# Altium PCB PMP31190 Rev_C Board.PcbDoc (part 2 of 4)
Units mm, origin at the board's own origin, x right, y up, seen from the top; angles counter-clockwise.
Board outline 175.26 x 91.44 mm, 4 copper layers (Top Layer, Mid-Layer 1, Mid-Layer 2, Bottom Layer), stack 1.473 mm thick; 252 components, 140 nets, 735 pads, 501 vias.
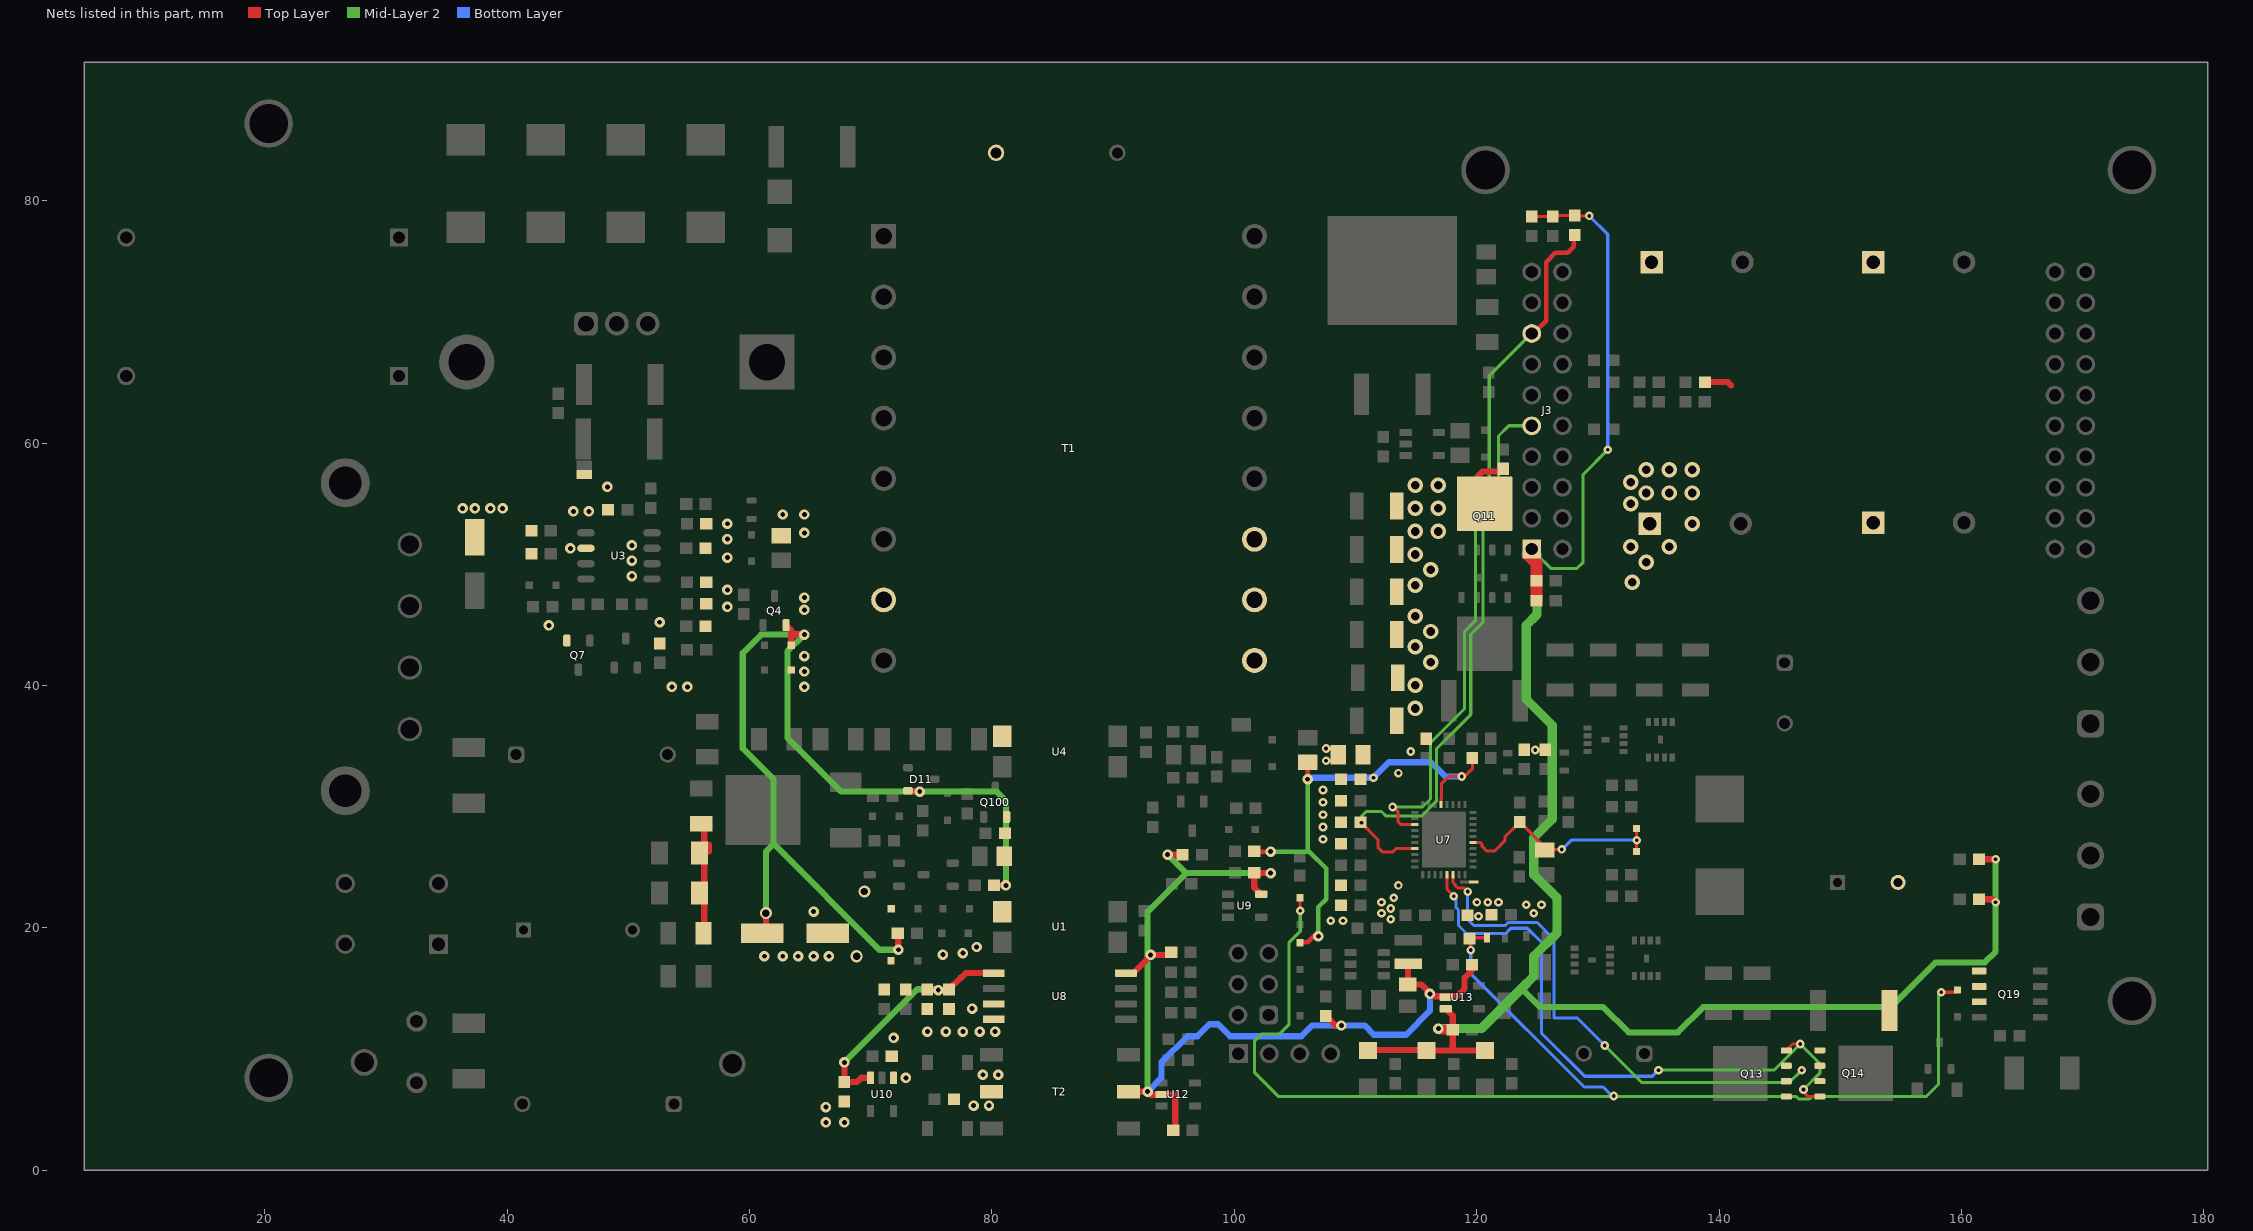
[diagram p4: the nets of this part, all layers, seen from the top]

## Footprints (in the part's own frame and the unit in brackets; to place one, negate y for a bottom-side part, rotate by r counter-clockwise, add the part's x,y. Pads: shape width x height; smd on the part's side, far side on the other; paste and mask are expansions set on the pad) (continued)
FP-750320256r00H_TRANSFORMER_41MM9_44MM0-MFG [mm]
  rrect5% 2.05x2.05 hole 1.35 paste-2539.97 mask+0: 1(-15.3,17.5)
  round 2.05 hole 1.35 paste-2539.97 mask+0: 2(-15.3,12.5) 3(-15.3,7.5) 4(-15.3,2.5) 5(-15.3,-2.5) 6(-15.3,-7.5) 7(-15.3,-12.5) 8(-15.3,-17.5) 9(15.3,-17.5) 10(15.3,-12.5) 11(15.3,-7.5) 12(15.3,-2.5) 13(15.3,2.5) 14(15.3,7.5) 15(15.3,12.5) 16(15.3,17.5)
  silkscreen extent -21.57,-22 20.95,22, body extent -21.05,-22.1 21.05,22.1, height 0.25
FP-560050316012_0603-MFG [mm]
  rrect20% 0.5x0.8 smd paste+0 mask+0: 1(-0.75,0) 2(0.75,0)
  silkscreen extent -0.13,-0.48 0.13,0.48, body extent -1.1,-0.58 1.1,0.58, height 0.25
FP-EKZM350ELL681MJ25S_RADIAL-MFG [mm]
  rrect8% 1.25x1.25 hole 0.75 paste-2539.97 mask+0: 1(-2.5,0)
  round 1.25 hole 0.75 paste-2539.97 mask+0: 2(2.5,0)
  silkscreen extent -5.25,-5.25 5.25,5.25, body extent -5.35,-5.35 5.35,5.35, height 0.25
FP-SQ9407EY-T1_GE3_SO-8-MFG [mil]
  rrect18% 47x22 smd paste+0 mask+0: 1(-99.5,75) 2(-99.5,25) 3(-99.5,-25) 4(-99.5,-75) 5(99.5,-75) 6(99.5,-25) 7(99.5,25) 8(99.5,75)
  silkscreen extent -149,-98 61,98, body extent -127,-102 127,102, height 10
FUSE_392 [mm] "LITTELFUSE"
  round 1.7 hole 1.05: 1(-2.54,0) 2(2.54,0)
  silkscreen extent -4.32,-2.03 4.32,2.03, body extent -4.25,-2 4.25,2, height 8
GBU [mm] "Comchip / Diodes Inc diode bridge"
  round 2 hole 1.5: 1(-7.62,0) 2(-2.54,0) 3(2.54,0) 4(7.62,0)
  silkscreen extent -11.15,-2.28 11.15,1.28, body extent -11.15,-2.28 11.15,1.28, height 21.55
HSINK_V6560W [mm] "Heat Sink TO-220"
  round 4.05 hole 2.7: 1(-12.7,0) 2(12.7,0)
  body extent -15,-9 15,3, height 25
IEC_HighVoltage_Small [mm]
  silkscreen extent -2.72,-2.24 2.72,2.47
IEC_HotSurface_Small [mm]
  silkscreen extent -2.72,-2.36 2.72,2.35
Keystone5012 [mil] "Keystone Multipurpose loops"
  round 87 hole 63: 1(0,0)
  silkscreen extent -70,-70 70,70, body extent -63,-63 63,62, height 319
MINI-SMA [mm] "COMCHIP"
  rect 1.4x1.9 smd: 1(-1.65,0) 2(1.65,0)
  silkscreen extent -3,-1.3 2.4,1.3, body extent -1.95,-0.9 1.95,0.9, height 1.7
Net-Tie_10milWide_30milLong [mil] "10mil net tie, no solder mask opening, no solder paste"
  rect 30x10 smd paste-5 mask-5: 1(-15,0) 2(15,0)
Net-Tie_50milWide_30milLong [mil] "50mil net tie, no solder mask opening, no solder paste"
  rect 30x50 smd paste-20 mask-20: 1(-15,0) 2(15,0)
Power_WDFN-8 [mm] "SMD, 8-Leads, Body 3.3x3.3mm, Pitch 0.65mm"
  rect 0.66x0.42 smd: 1(-1.47,0.975) 2(-1.47,0.325) 3(-1.47,-0.325) 4(-1.47,-0.975) 5(1.47,-0.975) 6(1.47,-0.325) 7(1.47,0.325) 8(1.47,0.975) 9(0,0)
  Top Layer region: 0.25,1.73 -0.32,1.73 -0.32,1.185 -0.5,1.185 -0.5,-1.185 -0.32,-1.185 -0.32,-1.73 0.25,-1.73 0.25,-1.185 1.33,-1.185 1.33,1.185 0.25,1.185
  silkscreen extent -1.9,-1.65 1.65,1.75, body extent -1.65,-1.65 1.65,1.65, height 0.81
RRV0036A-MFG [mm]
  rrect40% 0.6x0.25 smd paste+0 mask+0: 1(-2.4,2.25) 2(-2.4,1.75) 3(-2.4,1.25) 4(-2.4,0.75) 5(-2.4,0.25) 6(-2.4,-0.25) 7(-2.4,-0.75) 8(-2.4,-1.25) 9(-2.4,-1.75) 10(-2.4,-2.25) 19(2.4,-2.25) 20(2.4,-1.75) 21(2.4,-1.25) 22(2.4,-0.75) 23(2.4,-0.25) 24(2.4,0.25) 25(2.4,0.75) 26(2.4,1.25) 27(2.4,1.75) 28(2.4,2.25)
  rrect40% 0.25x0.6 smd paste+0 mask+0: 11(-1.75,-2.9) 12(-1.25,-2.9) 13(-0.75,-2.9) 14(-0.25,-2.9) 15(0.25,-2.9) 16(0.75,-2.9) 17(1.25,-2.9) 18(1.75,-2.9) 29(1.75,2.9) 30(1.25,2.9) 31(0.75,2.9) 32(0.25,2.9) 33(-0.25,2.9) 34(-0.75,2.9) 35(-1.25,2.9) 36(-1.75,2.9)
  rrect3% 3.6x4.6 smd paste-1000 mask+0: 37(0,0)
  silkscreen extent -3.4,-3.05 2.55,3.05, body extent -2.8,-3.3 2.8,3.3, height 0.25
Samtec_HTSW-103-07-x-D [mm] "Header, 2.54mm, 3x2, Gold, TH"
  rrect50% 1.55x1.55 hole 1.02: 1(-1.27,2.54)
  round 1.55 hole 1.02: 2(1.27,2.54) 3(-1.27,0) 4(1.27,0) 5(-1.27,-2.54) 6(1.27,-2.54)
  silkscreen extent -2.61,-3.91 2.61,4.3, body extent -2.51,-3.81 2.51,3.81, height 8.38
SMA [mm] "Molded Diode, 2-Leads, Body 4.3x2.6mm, IPC Medium Density, based on OnSemi component dimensions and land pattern"
  rect 2x2 smd: 1(-2,0) 2(2,0)
  silkscreen extent -3.66,-1.57 2.79,1.57, body extent -2.6,-1.3 2.6,1.3, height 2.42
SMC_265 [mm] "SMD, 2-Leads, Body 7.15x6.25mm"
  rect 2.6x3.2 smd: 1(-3.6,0) 2(3.6,0)
  silkscreen extent -5.6,-3.23 5.3,3.22, body extent -4.07,-3.13 4.07,3.13, height 2.65
SMD-4 [mm] "SMD, 4-Leads, Body 4.83x6.81mm, Pitch 2.54mm"
  rect 1.525x1.78 smd: 1(-4.763,1.27) 2(-4.763,-1.27) 3(4.763,-1.27) 4(4.763,1.27)
  silkscreen extent -3.5,-2.42 3.41,2.8, body extent -5.02,-2.42 5.02,2.42, height 3.91
SOD-123 [mm] "On Semi recommended land pattern"
  rect 0.915x1.22 smd: 1(-1.637,0) 2(1.637,0)
  silkscreen extent -2.74,-1.17 2.03,1.17, body extent -1.93,-0.9 1.93,0.9, height 1.35
SOD-323 [mm] "NXP recommended land pattern"
  rect 0.6x0.6 smd paste-0.05: 1(-1.1,0) 2(1.1,0)
  silkscreen extent -2.06,-0.86 1.53,0.86, body extent -1.3,-0.67 1.3,0.68, height 1.1
SOD-323F [mm] "NXP recommended land pattern"
  rect 0.6x0.6 smd paste-0.05: 1(-1.1,0) 2(1.1,0)
  silkscreen extent -2.06,-0.86 1.53,0.86, body extent -1.35,-0.67 1.35,0.68, height 0.79
SOT-23 [mm] "SOT23, 3-Leads, Body 2.9x1.3mm, Pitch 0.95mm, Lead Span 2.5mm, IPC Medium Density"
  rrect50% 1x0.6 smd: 1(-1.2,0.95) 2(-1.2,-0.95) 3(1.2,0)
  silkscreen extent -1.62,-1.5 0.7,1.5, body extent -1.16,-1.45 1.21,1.45, height 1
SOT-23L [mm] "SOT23, 3-Leads, Body 2.9x1.3mm, Pitch 0.95mm, Lead Span 2.5mm, IPC High Density"
  rrect50% 0.8x0.6 smd: 1(-1.1,0.95) 2(-1.1,-0.95) 3(1.1,0)
  silkscreen extent -1.5,-1.5 0.7,1.5, body extent -1.16,-1.45 1.21,1.45, height 1
TO-220FP [mm] "FM, Body 10.4x4.6mm, Pitch 2.55mm"
  rrect50% 1.95x1.95 hole 1.3: 1(-2.55,0)
  round 1.95 hole 1.3: 2(0,0) 3(2.55,0)
  silkscreen extent -5.1,-1.5 5.08,3, body extent -5.09,-1.5 5.09,3, height 19.41
WCAP-FTX2_1500x850 [mm] "TH, 2-Leads, Body 15x8.5mm"
  rrect50% 1.35x1.35 hole 0.9: 1(-6.25,0)
  round 1.35 hole 0.9: 2(6.25,0)
  body extent -7.5,-4.25 7.5,4.25, height 14
WCAP-PTHT_1000x1250 [mm] "TH, 2-Leads, Dia 10mm, Lead Sapcing 5mm"
  rrect50% 1.35x1.35 hole 0.9: 1(-2.5,0)
  round 1.35 hole 0.9: 2(2.5,0)
  body extent -5.25,-5.25 5.26,5.25, height 14.01
WE-CMB_Type_S [mm] "TH, 4-Leads, Body 14.7x13mm"
  rect 1.6x1.6 hole 1.1: 1(-3.85,2.5)
  round 1.6 hole 1.1: 2(-3.85,-2.5) 3(3.85,-2.5) 4(3.85,2.5)
  silkscreen extent -7.8,-6.5 7.35,6.5, body extent -7.77,-6.5 7.77,6.5, height 20
WE-HC6 [mm] "Wurth Electronik recommended land pattern"
  rect 3.85x4 smd: 1(-3.825,0) 2(3.825,0)
  silkscreen extent -6.2,-6.2 6.2,6.2, body extent -5.76,-5.36 5.74,5.34, height 5
WE-MAPI_2510 [mm] "SMD, 2-Leads, Body 2.7x2.2mm"
  rect 0.85x2.3 smd: 1(-0.975,0) 2(0.975,0)
  silkscreen extent -0.15,-1.1 0.15,1.1, body extent -1.25,-1 1.25,1, height 1
WL_SMCW_GREEN_1206 [mm] "SMD, 2-Leads, Body 3.2x1.6mm, Pitch 3mm"
  rect 1.4x1.5 smd: 1(-1.5,0) 2(1.5,0)
  silkscreen extent -2.9,-1.1 2.2,1.1, body extent -1.6,-0.85 1.6,0.85, height 0.78
Wurth_750313638 [mm] "SMD, 6-Leads, Body 8x9.14mm, Pitch 3.05mm"
  rect 1.9x1.14 smd: 1(-5.655,3.05) 2(-5.655,0) 3(-5.655,-3.05) 4(5.655,-3.05) 5(5.655,0) 6(5.655,3.05)
  silkscreen extent -4,-4.57 4,4.88, body extent -6.35,-4.57 6.35,4.57, height 7.62
Wurth_691236510003 [mm] "Terminal Block, 5.08mm, 3x1, R/A, TH"
  rrect50% 2.25x2.25 hole 1.5: 1(-5.08,0)
  round 2.25 hole 1.5: 2(0,0) 3(5.08,0)
  body extent -8.22,-5.5 7.62,5.85, height 18

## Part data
C1: library part CMP-0077651-1, "CAP, Safety, 2200 pF, 250VAC,+/- 20%, X1-Y1, D9xT4mm", Cap_Case=9x4x10mm, Manufacturer=MuRata, Supplier Part Number 1=490-DE1E3RA222MA4BN01F-ND, TempCo=B, Tolerance_%=10%, ValueDisplayed=2200pF
C2 C3: library part CMP-0012429-3, "CAP, Film, 0.68 uF, 630 V, +/- 20%, TH", Manufacturer=TDK, Supplier Part Number 1=495-4208-ND, Tolerance_%=20%, Value1=Unknown, Value2=630V, ValueDisplayed=0.68uF
C4 C5: library part CMP-0084596-1, "CAP, Film, 0.33 µF, X2 275 VAC, +/- 10%, TH", Cap_Case=15x8.5mm, Manufacturer="Wurth Elektronik", Tolerance_%=10%, ValueDisplayed=0.33µF
C6 C17 C51 C58 C70 C72 C73: library part CMP-0064933-4, "CAP, CERM, 1000 pF, 50 V,+/- 10%, X7R, 0603", Cap_Case=0603, Manufacturer="Wurth Elektronik", Supplier Part Number 1=732-8001-1-ND, TempCo=X7R, Tolerance_%=10%, Value1=Unknown, Value2=50V, ValueDisplayed=1000pF
C7 C8 C9 C10: library part CMP-0010013-3, "CAP, AL, 2200 uF, 50 V, +/- 20%, 0.018 ohm, TH", AC_Derating=0.35, Manufacturer=Rubycon, Tolerance_%=20%, Value1="0.018 ohm", Value2=50V, ValueDisplayed=2200uF
C11: library part CMP-0010802-1, "CAP, AL, 22 uF, 35 V, +/- 20%, SMD", Cap_Case=E55, Manufacturer=Wuerth, Tolerance_%=20%, Value1=Unknown, Value2=35V, ValueDisplayed=22uF
C12 C16 C62 C76 C100: library part CMP-0007696-2, "CAP, CERM, 1 uF, 50 V, +/- 10%, X7R, 0805", Cap_Case=0805, Manufacturer="Wurth Elektronik", Supplier Part Number 1=710-885012207103, TempCo=X7R, Tolerance_%=10%, Value1=Unknown, Value2=50V, ValueDisplayed=1uF
C13: library part CMP-0010800-1, "CAP, AL, 100 uF, 35 V, +/- 20%, SMD", Cap_Case=F80, Manufacturer=Panasonic, Tolerance_%=20%, Value1=Unknown, Value2=35V, ValueDisplayed=100uF
C14: library part CMP-0007872-2, Cap_Case=0805, Manufacturer=TDK, TempCo=X7R, Tolerance_%=10%, Value1=Unknown, Value2=50V
C15: library part CMP-0006825-5, "CAP, CERM, 2.2 uF, 16 V, +/- 20%, X5R, 0603", Cap_Case=0603, Manufacturer="Wurth Elektronik", Supplier Part Number 1=732-7915-1-ND, TempCo=X5R, Tolerance_%=20%, Value1=Unknown, Value2=16V, ValueDisplayed=2.2uF
C18 C22 C45 C46 C48 C49 C52 C55 C56 C59 C61 C64 C69 C77: library part CMP-0006837-3, "CAP, CERM, 0.1 uF, 50 V, +/- 10%, X7R, 0603", Cap_Case=0603, Manufacturer="Wurth Elektronik", TempCo=X7R, Tolerance_%=10%, Value1=Unknown, Value2=50V, ValueDisplayed=0.1uF
C19: library part CMP-0008950-2, "CAP, CERM, 10 uF, 25 V, +/- 10%, X5R, 1206", Cap_Case=1206, Manufacturer=Wuerth, TempCo=X5R, Tolerance_%=10%, Value1="0.004 ohm", Value2=25V, ValueDisplayed=10uF
C20 C23: library part CMP-0006761-4, "CAP, CERM, 10 pF, 50 V, +/- 5%, C0G/NP0, 0603", Cap_Case=0603, Manufacturer=Wuerth, TempCo=C0G/NP0, Tolerance_%=5%, Value1="0.403 ohm", Value2=50V, ValueDisplayed=10pF
C21: library part CMP-0006822-4, "CAP, CERM, 100 pF, 50 V, +/- 5%, C0G/NP0, 0603", Cap_Case=0603, Manufacturer="Wurth Elektronik", TempCo=C0G/NP0, Tolerance_%=5%, Value1=Unknown, Value2=50V, ValueDisplayed=100pF
C24: library part CMP-0085252-1, "CAP, CERM, 0.047 µF, 50 V,+/- 5%, X7R, 0603", Cap_Case=0603, Manufacturer=Wuerth, TempCo=X7R, Tolerance_%=5%, Value2=50V, ValueDisplayed=0.047µF
C25: library part CMP-0007975-2, "CAP, CERM, 2.2 uF, 25 V, +/- 10%, X7R, AEC-Q200 Grade 1, 0805", Cap_Case=0805, Manufacturer=TDK, Supplier Part Number 1=445-6965-1-ND, TempCo=X7R, Tolerance_%=10%, Value1=Unknown, Value2=25V, ValueDisplayed=2.2uF
C26: library part CMP-0750039-1, "CAP, CERM, 0.01 µF, 50 V,+/- 10%, X7R, 0603", Cap_Case=0603, Manufacturer="Wurth Elektronik", TempCo=X7R, Tolerance_%=10%, Value2=50V, ValueDisplayed=0.01µF
C29 C30 C31 C32 C36 C37 C38 C39 C40 C41 C42 C43: library part CMP-0081135-1, "CAP, CERM, 10 µF, 50 V,+/- 10%, X7R, 1210", Cap_Case=1210, Manufacturer=Wuerth, TempCo=X7R, Tolerance_%=10%, Value1="0.001 ohm", Value2=50V, ValueDisplayed=10µF
C33 C44: library part CMP-0079638-1, "CAP, Aluminum Polymer, 100 µF, 35 V,+/- 20%, 0.022 ohm, TH", Cap_Case=10x14mm, Manufacturer="Wurth Elektronik", Supplier Part Number 1=732-11917-1-ND, Tolerance_%=20%, Value1="0.022 ohm", Value2=35V, ValueDisplayed=100µF
C34 C35: library part CMP-0007097-4, "CAP, CERM, 0.47 uF, 50 V, +/- 10%, X7R, AEC-Q200 Grade 1, 0603", Cap_Case=0603, Manufacturer=TDK, Supplier Part Number 1=445-172475-1-ND, TempCo=X7R, Tolerance_%=10%, Value1=Unknown, Value2=50V, ValueDisplayed=0.47uF
C47: library part CMP-0007696-2, "CAP, CERM, 4.7 uF, 25 V, +/- 10%, X5R, 0805", Cap_Case=0805, Manufacturer="Wurth Elektronik", TempCo=X5R, Tolerance_%=10%, Value1=Unknown, Value2=25V, ValueDisplayed=4.7uF
C50 C53 C54 C57 C60 C65 C66 C67 C68: library part CMP-0006833-4, "CAP, CERM, 1 uF, 25 V, +/- 10%, X7R, 0603", Cap_Case=0603, Manufacturer="Wurth Elektronik", Supplier Part Number 1=732-7994-1-ND, TempCo=X7R, Tolerance_%=10%, Value1=Unknown, Value2=25V, ValueDisplayed=1uF
C63: library part CMP-0078154-1, "CAP, CERM, 10 µF, 16 V,+/- 20%, X5R, 0805", Cap_Case=0805, Manufacturer="Wurth Elektronik", Supplier Part Number 1=732-7624-1-ND, TempCo=X5R, Tolerance_%=20%, Value2=16V, ValueDisplayed=10µF
C74 C75: library part CMP-0081135-1, "CAP, CERM, 10 µF, 50 V,+/- 10%, X7R, 1210", Cap_Case=1210, Manufacturer=MuRata, Supplier Part Number 1=490-10961-1-ND, TempCo=X7R, Tolerance_%=10%, Value1="0.001 ohm", Value2=50V, ValueDisplayed=10µF
C101: library part CMP-0001423-1, "Cap Aluminum 470uF 35V 20% (10 X 16mm) Radial 5mm", Leakage Current=238uA, Manufacturer="United Chemi-Con", Operating Temperature Range="-40°C to +105°C", Tolerance_%=20%, ValueDisplayed=470µF
D1 D2 D12 D13 D16: library part CMP-0077069-2, "Diode, Standard Recovery Rectifier, 250 V, 0.2 A, SOD-323", Manufacturer="Micro Commercial Components", Value1=0.2A, Value2=1.25V
D3: library part CMP-0029241-1, "Diode, P-N-Bridge, 600 V, 4 A, TH", Manufacturer="Micro Commercial Components", Supplier Part Number 1=GBU4J-BPMS-ND, Value1=4A, Value2=1V
D4 D5 D103 D104: library part CMP-0005730-3, "Diode, TVS, Uni, 43 V, 69.4 Vc, SMC", Manufacturer="Wuerth Electronic", Value1=1500W
D6: library part CMP-0029033-2, "Diode, Ultrafast, 600 V, 1 A, AEC-Q101, SMA", Manufacturer="ON Semiconductor", Value1=1A, Value2=1.05V
D7: library part CMP-0005835-4, "Diode, Zener, 18 V, 200 mW, SOD-323", Manufacturer="Central semiconductor", Power_W=200mW, Value1=0.2W
D8 D15: library part CMP-0085758-1, "Diode, Zener, 12 V, 300 mW, SOD-323", Manufacturer="Central semiconductor", Power_W=300mW, Value1=0.3W
D9 D10: library part CMP-0076945-2, "Diode, P-N, 600 V, 1 A, MINI-SMA", Manufacturer="Taiwan semiconductor corporation", Value1=1A, Value2=1.1V
D11: library part CMP-0077061-2, "Diode, Switching, 70 V, 0.25 A, AEC-Q101, SOT-23", Manufacturer=Vishay-Semiconductor, Value1=0.25A, Value2=1.25V
D14 D25 D29 D100: library part CMP-0005833-4, "Diode, Zener, 15 V, 200 mW, SOD-323", Manufacturer="Central semiconductor", Power_W=200mW, Value1=0.2W
D17: library part CMP-0005839-4, "Diode, Zener, 27 V, 200 mW, SOD-323", Manufacturer="Diodes Inc.", Power_W=200mW, Value1=0.2W
D18 D19 D26 D27 D28: library part CMP-0076946-2, "Diode, Schottky, 100 V, 0.25 A, SOD-323F", Manufacturer=Nexperia, Value1=0.25A, Value2=0.85V
D20 D21 D22: library part CMP-0002936-3, "LED, Green, SMD", Color=Green, Manufacturer="Wurth Elektronik", Power_TotalModule=72mW, Value1=0.072W, Value2=2V
D23 D24: library part CMP-0028525-2, "Diode, Schottky, 30 V, 0.5 A, SOD-123", Manufacturer="ON Semiconductor", Value1=0.5A, Value2=0.43V
D30: library part CMP-0005786-2, "Diode, Zener, 5.1 V, 500 mW, SOD-123", Manufacturer="ON Semiconductor", Power_W=500mW, Value1=0.5W
D31: library part CMP-0076970-1, "Diode, Schottky, 40 V, 0.2 A, SOT-23", Manufacturer="Diodes Inc.", Supplier Part Number 1=BAS40-04FDICT-ND, Value1=0.2A, Value2=1V
D101: library part CMP-0076946-2, "Diode, Schottky, 100 V, 0.25 A, SOD-323F", Manufacturer=Nexperia, PartNumber=BAT46WJ,115, Value1=0.25A, Value2=0.85V
D102: library part CMP-0085758-1, "Diode, Zener, 28 V, 250 mW, SOD-323", Manufacturer="Central semiconductor", Power_W=250mW, Value1=0.25W
F1: library part CMP-0003561-2, "Fuse, 3.15 A, 250VAC/VDC, TH", Irating_A=3.15A, Manufacturer=Littelfuse, Supplier Part Number 1=F5504CT-ND
H1: library part CMP-0086362-1, "Heat Sink TO-220", Manufacturer="Assman WSW"
H2: library part CMP-0095825-2, "Heat Sink Passive TO-220 Straight Copper 12.5°C/W Matte Tin", Digikey Part Number=6230DG(COPPER)-ND, Manufacturer=Aavid, Mating Package=TO-220, Mouser Part Number=532-6230DG, Operating Temperature Range=to
J1 J2: library part CMP-0079043-1, "Terminal Block, 5.08mm, 3x1, R/A, TH", Color=Green, Current_A=20A, Manufacturer="Wurth Elektronik", Supplier Part Number 1=732-10996-ND, Voltage_V=300V
J3: library part CMP-0003837-4, "Receptacle, 2.54mm, 10x2, Tin, TH", Alternate Manufacturer="Major League Electronics", Alternate PartNumber=CRD-081413-A-G, Manufacturer=Wuerth
J4: library part CMP-0078266-4, "Receptacle, 2.54mm, 10x2, Tin, TH", Alternate Manufacturer="Major League Electronics", Alternate PartNumber=CRD-081413-A-G, Manufacturer=Wuerth
J5: library part CMP-0089047-1, Current_A=4A, Manufacturer=Molex, Voltage_V=500V
J6: library part CMP-0055587-1, "Header, 2.54mm, 3x2, Gold, TH", Color=Natural, Manufacturer=Samtec, Supplier Part Number 1=HTSW-103-07-G-D-ND
L1: library part CMP-0091284-1, "300µH Unshielded Toroidal Inductor 2.5A 150mOhm Max Radial, Vertical (Open)", Manufacturer="Wurth Electronics", Operating Temperature Range="-40°C to +105°C", Test Frequency=10kHz, Tolerance_%=20%
L2: library part CMP-0013143-1, "Coupled inductor, 2.2 mH,  A, 0.07 ohm, TH", Manufacturer="Wurth Elektronik", Supplier Part Number 1=732-1440-ND, ValueDisplayed=2.2mH
L3: library part CMP-0063967-1, "Inductor, Shielded Drum Core, Superflux, 5.5 uH, 10 A, 0.0112 ohm, SMD", Manufacturer="Wurth Elektronik", Supplier Part Number 1=732-1171-1-ND, Value1="0.0112 ohm", Value2=10A, ValueDisplayed=5.5uH
L4: library part CMP-0750073-1, "Inductor, Shielded, Metal Composite, 10 µH, 0.6 A, 0.733 ohm, SMD", Manufacturer="Wurth Elektronik", Value1="0.733 ohm", Value2=0.6A, ValueDisplayed=10µH
LOGO1 LOGO2 LOGO3 LOGO4: library part CMP-0074835-1, "IEC 61010-1 High Voltage Warning"
Logo5: library part CMP-0074837-2, "IEC 61010-1 Hot Surface Warning", Manufacturer="Texas Instruments"
NT1 NT2: library part CMP-0078142-5, "Single point connection between nets.", Manufacturer=N/A
Q1 Q3 Q4 Q7 Q100: library part CMP-0000387-2, "Transistor, NPN, 40 V, 0.2 A, SOT-23", Manufacturer="Diodes Inc.", Supplier Part Number 1=MMBT3904-FDICT-ND, Value1="0.2 A", Value2=400
Q2: library part CMP-0001269-3, "MOSFET, N-CH, 560 V, 7.6 A, DPAK", Alternate Manufacturer=None, Manufacturer="Infineon Technologies", Value1=1, Value2="26 nC"
Q5: library part CMP-0001215-2, "MOSFET, N-CH, 150 V, 101 A, DDPAK", Alternate Manufacturer=None, Manufacturer="On semi", Value2="53 nC"
Q6: library part CMP-0067578-2, "MOSFET, N-CH, 650 V, 7 A, TO-220FP", Alternate Manufacturer=None, Manufacturer="Infineon Technologies", Value1="? ohm", Value2="20 nC"
Q8: library part CMP-0000326-2, "Transistor, PNP, 40 V, 0.2 A, SOT-23", Manufacturer="Diodes Inc.", Supplier Part Number 1=MMBT3906-FDICT-ND, Value1="0.2 A", Value2=400
Q11 Q12 Q13 Q14: library part CMP-0000817-1, "MOSFET, N-CH, 60 V, 50 A, DQJ0008A (VSONP-8)", Alternate Manufacturer=None, Manufacturer="Texas Instruments", Supplier Part Number 1=296-35583-1-ND, Value1=0.009, Value2="22 nC"
Q15 Q16 Q17 Q18: library part CMP-0000855-1, "MOSFET, N-CH, 60 V, 70 A, 8-PowerWDFN", Alternate Manufacturer=None, Manufacturer="ON Semiconductor", Value1=0.013, Value2="9 nC"
Q19: library part CMP-0093692-1, "P-Channel 60 V 4.6A (Tc) 3.75W (Tc) Surface Mount 8-SOIC", Digikey Part Number=846-RS3L110ATTB1TR-ND, Drain To Source Breakdown Voltage=-60V, Input Capacitace At Vds="6300pF @ -30V", Manufacturer="Rohm Semiconductor", Operating Temperature Range="-55°C to +175°C", Power_W=1.4W, Pulse Drain Current=-44A, Typ Forward Diode Voltage=-0.84V
R1: library part CMP-0023129-5, "RES, 470, 1%, 0.1 W, 0603", Manufacturer=Yageo, Power_W=100mW, Supplier Part Number 1=311-470HRCT-ND, TempCo="100 ppm/C", Tolerance_%=1%, Value2=0.1W, Value_Code=470R, ValueDisplayed=470
R2 R4: library part CMP-0018758-2, "RES, 0, 5%, 0.25 W, 1206", Manufacturer=Rohm, Power_W=250mW, Supplier Part Number 1=RHM0.0ERCT-ND, TempCo="200 ppm/C", Tolerance_%=5%, Value2=0.25W, Value_Code=0000, ValueDisplayed=0
R3 R5: library part CMP-0017631-3, "RES, 499 k, 1%, 0.25 W, AEC-Q200 Grade 0, 1206", Manufacturer=Panasonic, Power_W=250mW, Supplier Part Number 1=P499KFCT-ND, TempCo="100 ppm/C", Tolerance_%=1%, Value2=0.25W, Value_Code=499k
R6 R9 R10 R11 R23 R33 R62 R63 R64: library part CMP-0022895-5, "RES, 1.00 k, 1%, 0.1 W, 0603", Manufacturer=Yageo, Power_W=100mW, Supplier Part Number 1=311-1.00KHRCT-ND, TempCo="100 ppm/C", Tolerance_%=1%, Value2=0.1W, Value_Code=1k00, ValueDisplayed=1.00k
R7 R8: library part CMP-0016196-2, "RES, 4.7, 5%, 1 W, 2010", Manufacturer=Bourns, Power_W=1W, Supplier Part Number 1=652-CRM2010JW4R7ELF, TempCo="100 ppm/C", Tolerance_%=5%, Value_Code=4R70, ValueDisplayed=4.7
R12: library part CMP-0015987-3, "RES, 5.6, 5%, 1 W, AEC-Q200 Grade 0, 2512", Manufacturer=Vishay-Dale, Power_W=1W, Supplier Part Number 1=541-5.6XCT-ND, TempCo="200 ppm/C", Tolerance_%=5%, Value_Code=5R60, ValueDisplayed=5.6
R13 R47 R48 R53 R57: library part CMP-0087986-1, "WRIS-KSKE Thick Film Resistors", Manufacturer="Wurth Electronics", Power_W=250mW, TempCo=100ppm/°C, Tolerance_%=1%
R14 R20 R36 R80 R81 R82: library part CMP-0023152-5, "RES, 4.75 k, 1%, 0.1 W, 0603", Manufacturer=Yageo, Power_W=100mW, Supplier Part Number 1=311-4.75KHRCT-ND, TempCo="100 ppm/C", Tolerance_%=1%, Value2=0.1W, Value_Code=4k75, ValueDisplayed=4.75k
R15 R19 R70 R72: library part CMP-0018469-2, "RES, 750 k, 1%, 0.25 W, 1206", Manufacturer="Yageo America", Power_W=250mW, Supplier Part Number 1=311-750KFRCT-ND, TempCo="100 ppm/C", Tolerance_%=1%, Value2=0.25W, Value_Code=750k
R16: library part CMP-0025882-3, "RES, 100, 5%, 0.25 W, AEC-Q200 Grade 0, 0603", Manufacturer=Rohm, Power_W=250mW, Supplier Part Number 1=RHM100DCT-ND, TempCo="200 ppm/C", Tolerance_%=5%, Value2=0.25W, Value_Code=100R, ValueDisplayed=100
R17: library part CMP-0017631-3, Manufacturer=Panasonic, Power_W=250mW, TempCo="100 ppm/C", Tolerance_%=1%, Value2=0.25W
R18: library part CMP-0025011-2, "RES, 271 k, 0.5%, 0.1 W, 0603", Manufacturer="Yageo America", Power_W=100mW, TempCo="50 ppm/C", Tolerance_%=0.5%, Value2=0.1W, Value_Code=271k
R21 R88 R89 R94 R100 R101: library part CMP-0086261-1, "RES, 100 k, 0.5%, 0.1 W, AEC-Q200 Grade 0, 0603", Manufacturer=Vishay-Dale, Power_W=100mW, TempCo="50 ppm/C", Tolerance_%=0.5%, Value2=0.1W, Value_Code=100k
R22 R49 R50 R51 R52 R54 R90: library part CMP-0023343-3, "RES, 0, 1%, 0.1 W, AEC-Q200 Grade 0, 0603", Manufacturer="Stackpole Electronics Inc", Power_W=100mW, Supplier Part Number 1=RMCF0603ZT0R00CT-ND, TempCo=ppm/C, Tolerance_%=1%, Value2=0.1W, Value_Code=0
R24: library part CMP-0021627-3, "RES, 2.21 k, 1%, 0.125 W, AEC-Q200 Grade 0, 0805", Manufacturer=Panasonic, Power_W=125mW, Supplier Part Number 1=P2.21KCCT-ND, TempCo="100 ppm/C", Tolerance_%=1%, Value2=0.125W, Value_Code=2k21, ValueDisplayed=2.21k
R25: library part CMP-0023335-5, "RES, 9.53 k, 1%, 0.1 W, 0603", Manufacturer=Yageo, Power_W=100mW, Supplier Part Number 1=311-9.53KHRCT-ND, TempCo="100 ppm/C", Tolerance_%=1%, Value2=0.1W, Value_Code=9k53, ValueDisplayed=9.53k
R26: library part CMP-0022695-3, "RES, 30.0 k, 1%, 0.1 W, AEC-Q200 Grade 0, 0603", Manufacturer=Panasonic, Power_W=100mW, Supplier Part Number 1=P30.0KHCT-ND, TempCo="100 ppm/C", Tolerance_%=1%, Value2=0.1W, Value_Code=30k0, ValueDisplayed=30.0k
R27 R28: library part CMP-0015769-1, "RES, 0.5, 1%, 1 W, 2512", Manufacturer=Wuerth, Power_W=1W, TempCo="200 ppm/C", Tolerance_%=1%, Value_Code=R500, ValueDisplayed=0.5
R29: library part CMP-0022883-5, "RES, 1.50 k, 1%, 0.1 W, 0603", Manufacturer=Yageo, Power_W=100mW, Supplier Part Number 1=311-1.50KHRCT-ND, TempCo="100 ppm/C", Tolerance_%=1%, Value2=0.1W, Value_Code=1k50, ValueDisplayed=1.50k
R30 R37 R71 R73 R74 R76 R79 R86 R87: library part CMP-0022746-5, "RES, 10.0 k, 1%, 0.1 W, 0603", Manufacturer=Yageo, Power_W=100mW, Supplier Part Number 1=311-10.0KHRCT-ND, TempCo="100 ppm/C", Tolerance_%=1%, Value2=0.1W, Value_Code=10k0, ValueDisplayed=10.0k
R31: library part CMP-0022984-5, "RES, 2.21 k, 1%, 0.1 W, 0603", Manufacturer=Yageo, Power_W=100mW, Supplier Part Number 1=311-2.21KHRCT-ND, TempCo="100 ppm/C", Tolerance_%=1%, Value2=0.1W, Value_Code=2k21, ValueDisplayed=2.21k
R32: library part CMP-0025613-3, "RES, 86.6 k, 0.5%, 0.1 W, 0603", Manufacturer="Yageo America", Power_W=100mW, TempCo="50 ppm/C", Tolerance_%=0.5%, Value2=0.1W, Value_Code=86k6, ValueDisplayed=86.6k
R34: library part CMP-0023133-5, "RES, 47.0 k, 1%, 0.1 W, 0603", Manufacturer=Yageo, Power_W=100mW, Supplier Part Number 1=311-47.0KHRCT-ND, TempCo="100 ppm/C", Tolerance_%=1%, Value2=0.1W, Value_Code=47k0, ValueDisplayed=47.0k
R35: library part CMP-0022906-5, "RES, 20.0 k, 1%, 0.1 W, 0603", Manufacturer=Yageo, Power_W=100mW, Supplier Part Number 1=311-20.0KHRCT-ND, TempCo="100 ppm/C", Tolerance_%=1%, Value2=0.1W, Value_Code=20k0, ValueDisplayed=20.0k
R46: library part CMP-0015819-2, "RES, 0.002, 1%, 2 W, 2512", Manufacturer=Wuerth, Power_W=2W, TempCo=ppm/C, Tolerance_%=1%, Value_Code=2L000, ValueDisplayed=0.002
R55: library part CMP-0015814-2, "RES, 0.005, 1%, 2 W, 2512", Manufacturer=Wuerth, Power_W=2W, TempCo="100 ppm/C", Tolerance_%=1%, Value_Code=5L000, ValueDisplayed=0.005
R56: library part CMP-0022754-4, "RES, 113 k, 1%, 0.1 W, 0603", Manufacturer=Yageo, Power_W=100mW, Supplier Part Number 1=311-113KHRCT-ND, TempCo="100 ppm/C", Tolerance_%=1%, Value2=0.1W, Value_Code=113k
R58: library part CMP-0025067-3, "RES, 2.58 k, 0.5%, 0.1 W, 0603", Manufacturer="Yageo America", Power_W=100mW, TempCo="50 ppm/C", Tolerance_%=0.5%, Value2=0.1W, Value_Code=2k58, ValueDisplayed=2.58k
R59: library part CMP-0022941-4, "RES, 249 k, 1%, 0.1 W, 0603", Manufacturer=Yageo, Power_W=100mW, Supplier Part Number 1=311-249KHRCT-ND, TempCo="100 ppm/C", Tolerance_%=1%, Value2=0.1W, Value_Code=249k
R60: library part CMP-0022816-5, "RES, 15.0 k, 1%, 0.1 W, 0603", Manufacturer=Yageo, Power_W=100mW, Supplier Part Number 1=311-15.0KHRCT-ND, TempCo="100 ppm/C", Tolerance_%=1%, Value2=0.1W, Value_Code=15k0, ValueDisplayed=15.0k
R61: library part CMP-0025339-3, "RES, 4.22 k, 0.5%, 0.1 W, 0603", Manufacturer="Yageo America", Power_W=100mW, TempCo="50 ppm/C", Tolerance_%=0.5%, Value2=0.1W, Value_Code=4k22, ValueDisplayed=4.22k
R65: library part CMP-0023232-5, "RES, 66.5 k, 1%, 0.1 W, 0603", Manufacturer=Yageo, Power_W=100mW, Supplier Part Number 1=311-66.5KHRCT-ND, TempCo="100 ppm/C", Tolerance_%=1%, Value2=0.1W, Value_Code=66k5, ValueDisplayed=66.5k
R66: library part CMP-0022236-4, "RES, 24.3 k, 1%, 0.1 W, AEC-Q200 Grade 0, 0603", Manufacturer=Vishay-Dale, Power_W=100mW, Supplier Part Number 1=541-24.3KHCT-ND, TempCo="100 ppm/C", Tolerance_%=1%, Value2=0.1W, Value_Code=24k3, ValueDisplayed=24.3k
R67: library part CMP-0023155-5, "RES, 4.99 k, 1%, 0.1 W, 0603", Manufacturer=Yageo, Power_W=100mW, Supplier Part Number 1=311-4.99KHRCT-ND, TempCo="100 ppm/C", Tolerance_%=1%, Value2=0.1W, Value_Code=4k99, ValueDisplayed=4.99k
R68: library part CMP-0024096-3, "RES, 30.1 k, 0.1%, 0.1 W, 0603", Manufacturer="Yageo America", Power_W=100mW, TempCo="25 ppm/C", Tolerance_%=0.1%, Value2=0.1W, Value_Code=30k1, ValueDisplayed=30.1k
R69: library part CMP-0024368-2, "RES, 5.23 k, 0.1%, 0.1 W, 0603", Manufacturer="Yageo America", Power_W=100mW, TempCo="25 ppm/C", Tolerance_%=0.1%, Value2=0.1W, Value_Code=5k23, ValueDisplayed=5.23k
R75 R78: library part CMP-0022925-5, "RES, 22.0 k, 1%, 0.1 W, 0603", Manufacturer=Yageo, Power_W=100mW, Supplier Part Number 1=311-22.0KHRCT-ND, TempCo="100 ppm/C", Tolerance_%=1%, Value2=0.1W, Value_Code=22k0, ValueDisplayed=22.0k
R77: library part CMP-0023304-5, "RES, 88.7 k, 1%, 0.1 W, 0603", Manufacturer=Yageo, Power_W=100mW, Supplier Part Number 1=311-88.7KHRCT-ND, TempCo="100 ppm/C", Tolerance_%=1%, Value2=0.1W, Value_Code=88k7, ValueDisplayed=88.7k
R84 R85: library part CMP-0022008-4, "RES, 110 k, 1%, 0.1 W, AEC-Q200 Grade 0, 0603", Manufacturer=Vishay-Dale, Power_W=100mW, Supplier Part Number 1=541-110KHCT-ND, TempCo="100 ppm/C", Tolerance_%=1%, Value2=0.1W, Value_Code=110k
R93: library part CMP-0016277-2, "RES, 1.00 k, 1%, 0.75 W, AEC-Q200 Grade 0, 2010", Manufacturer=Vishay-Dale, Power_W=750mW, Supplier Part Number 1=541-1.00KACCT-ND, TempCo="100 ppm/C", Tolerance_%=1%, Value2=0.75W, Value_Code=1k00, ValueDisplayed=1.00k
R102: library part CMP-0022436-4, "RES, 475 k, 1%, 0.1 W, AEC-Q200 Grade 0, 0603", Manufacturer=Vishay-Dale, Power_W=100mW, Supplier Part Number 1=541-475KHCT-ND, TempCo="100 ppm/C", Tolerance_%=1%, Value2=0.1W, Value_Code=475k
T1: library part CMP-0096640-1, "Transformer 6:1 3000VAC 250uH 41.90x44.00x31.75mm", Frequency_Fixed=100kHz, Manufacturer="Wurth Electronics", Operating Temperature Range="-40°C to +125°C", Voltage_Isolation_Vrms=3kV
T2: library part CMP-0030600-1, "Transformer, 340 uH, TH", Manufacturer="Wurth Elektronik", ValueDisplayed="Np : Ns {} 1 : 1.3"
TP1 TP2: library part CMP-0055149-2, "Test Point, Multipurpose, White, TH", Color=White, Manufacturer="Keystone Electronics", Supplier Part Number 1=36-5012-ND
U1 U4: library part CMP-0006172-3, "Optocoupler, 5.3 kV, 63-125% CTR, SMT", Manufacturer=Vishay-Semiconductor, Supplier Part Number 1=751-1346-1-ND, Voltage_Isolation_Vrms=5.3kV
U2: library part CMP-0013050-3, "High-Frequency Multi-Mode Synchronous Rectifier Controller, DBV0005A (SOT-23-5)", Alternate Manufacturer="Texas Instruments", Alternate PartNumber=UCC24612-1DBVT
U3: library part CMP-0030003-1, "Transition Mode PFC Controller, 18 V, 0.075 mA Startup Current, -40 to 85 degC, 8-pin SOIC (D), Green (RoHS & no Sb/Br)", Manufacturer="Texas Instruments", Operating Supply Current(mA)=4, Operating Supply(Max)(V)=18, Practical Operating Frequency(Max)(MHz)=0.2, Rating=Catalog, Startup Current(mA)=0.075
U5: library part CMP-0033091-1, "Adjustable Precision Shunt Regulator, 34 ppm / degC, 100 mA, -40 to 85 degC, 3-pin SOT-23 (DBZ), Green (RoHS & no Sb/Br)", Manufacturer="Texas Instruments", Rating=Catalog, Temp Coeff(Max)(ppm/ degree C)=92, Temp Coeff(Typ)(ppm/ degree C)=34
U7: library part CMP-0093459-1, Manufacturer="Texas Instruments", Operating Temperature Range=to
U8: library part CMP-0078341-1, "Precision, 2-V Input, Reinforced Isolated Amplifier, DWV0008A (SOIC-8)", Alternate Manufacturer="Texas Instruments", Alternate PartNumber=AMC1311BDWV
U9: library part CMP-0073550-1, "1-MHz, Low-Power Operational Amplifier for Cost-Sensitive Systems, DBV0005A (SOT-23-5)", Alternate Manufacturer="Texas Instruments", Alternate PartNumber=TLV6001UIDBVT
U10: library part CMP-0035558-1, "Single Output LDO, 150 mA, Fixed 5 V Output, 2.5 to 24 V Input, with Ultra-Low IQ, 5-pin SOT-23 (DBV), -40 to 125 degC, Green (RoHS & no Sb/Br)", Manufacturer="Texas Instruments"
U11: library part CMP-0065101-3, "4V to 36 V 0.6 A Synchronous Step-Down Converter, DBV0006A (SOT-23-6)", Alternate Manufacturer="Texas Instruments", Alternate PartNumber=TPS560430YDBVT
U12: library part CMP-0065840-1, "Low-Noise 350 mA, 410 kHz Transformer Driver, DBV0005A (SOT-23-5)", Alternate Manufacturer="Texas Instruments", Alternate PartNumber=SN6501DBVT
U13: library part CMP-0035588-1, "Single Output LDO, 150 mA, Fixed 3.3 V Output, 2.5 to 24 V Input, with Ultra-Low IQ, 5-pin SOT-23 (DBV), -40 to 125 degC, Green (RoHS & no Sb/Br)", Manufacturer="Texas Instruments"

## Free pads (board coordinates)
  round 4 hole 3.2: 2(20.32,7.62) 2(20.32,86.36) 2(120.726,82.54) 2(174.066,13.96) 2(174.066,82.54)

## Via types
v1: diameter 0.711, hole 0.305, Top Layer to Bottom Layer, 109 vias
v2: diameter 0.864, hole 0.406, Top Layer to Bottom Layer, 105 vias
v3: diameter 1.27, hole 0.711, Top Layer to Bottom Layer, 72 vias
v4: diameter 0.864, hole 0.406, Top Layer to Bottom Layer, tented both sides, 40 vias
v5: diameter 1.016, hole 0.508, Top Layer to Bottom Layer, 38 vias
v6: diameter 1, hole 0.6, Top Layer to Bottom Layer, 26 vias
v7: diameter 0.6, hole 0.3, Top Layer to Bottom Layer, tented top, 24 vias
v8: diameter 0.711, hole 0.305, Top Layer to Bottom Layer, tented both sides, 22 vias
v9: diameter 0.711, hole 0.305, Top Layer to Bottom Layer, tented top, 21 vias
v10: diameter 0.5, hole 0.2, Top Layer to Bottom Layer, 16 vias
v11: diameter 0.864, hole 0.406, Top Layer to Bottom Layer, tented top, 12 vias
v12: diameter 1, hole 0.6, Top Layer to Bottom Layer, tented top, 9 vias
v13: diameter 1, hole 0.6, Top Layer to Bottom Layer, tented both sides, 5 vias
v14: diameter 0.6, hole 0.3, Top Layer to Bottom Layer, 1 vias
v15: diameter 0.711, hole 0.305, Top Layer to Bottom Layer, tented bottom, 1 vias

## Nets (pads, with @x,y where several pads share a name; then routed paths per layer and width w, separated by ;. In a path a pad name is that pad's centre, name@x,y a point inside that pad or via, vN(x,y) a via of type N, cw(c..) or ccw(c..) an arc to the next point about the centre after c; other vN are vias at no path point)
+3V3: C65.2 C68.2 C69.2 D20.2 D21.2 D22.2 J3.1 R80.2 R81.2 R82.2 R88.2 R89.2 U13.3 | length 161.1
  Top Layer w0.254: R80.2@124.53,78.698 R81.2@126.289,78.698 126.359,78.769 R82.2@128.104,78.769 128.133,78.74 v1(129.286,78.74)
  Top Layer w0.508: D20.2@111.04,9.883 111.102,9.883 111.125,9.906 115.843,9.906 D21.2@115.866,9.883 117.983,9.883 ; U13.3@117.448,13.325 118.023,12.75 C65.2@118.023,11.568 ; C65.2@117.983,11.557 117.994,11.568 C65.2@118.023,11.568 ; D22.2@120.695,9.883 117.983,9.883 ; J3.1@124.206,50.8 124.53,51.124 J3.1@124.53,51.267 ; R88.2@161.455,22.352 162.56,22.352 v1(162.814,22.098) ; R89.2@161.455,25.654 v1(162.814,25.654) ; 117.983,9.883 118.023,9.923 C65.2@118.023,11.568
  Top Layer w0.762: v2(116.84,11.684) 116.967,11.557 C65.2@117.983,11.557
  Top Layer w1.016: J3.1@124.206,50.8 124.925,50.081 C69.2@124.925,48.63 C68.2@124.925,46.99
  Mid-Layer 2 w0.254: J3.1@124.587,51.181 124.968,50.8 126.111,49.657 128.27,49.657 128.778,50.165 128.778,57.404 v9(130.81,59.436)
  Mid-Layer 2 w0.508: 123.698,14.986 125.222,13.462 130.429,13.462 132.524,11.367 136.588,11.367 138.684,13.462 154.178,13.462 157.861,17.145 161.925,17.145 162.814,18.034 v1(162.814,22.098) v1(162.814,25.654)
  Mid-Layer 2 w0.762: v2(116.84,11.684) 120.396,11.684 123.698,14.986 124.714,16.002 124.714,17.653 126.619,19.558 126.619,22.479 124.714,24.384 124.714,27.432 126.238,28.956 126.238,36.703 124.079,38.862 124.079,44.958 124.968,45.847 J3.1@124.968,50.8 ; J3.1@124.53,51.267 124.53,51.238 J3.1@124.587,51.181
  Bottom Layer w0.254: v1(129.286,78.74) 130.81,77.216 v9(130.81,59.436)
+5Vp: C54.2 C55.2 C60.2 U8.1 U10.3 | length 20.4
  Top Layer w0.508: v2(67.818,8.89) C60.2@67.818,7.277 68.872,7.277 69.215,7.62 69.977,7.62 U10.3@69.979,7.622 U10.3@69.852,7.622 ; C55.2@74.676,14.897 74.695,14.878 75.546,14.878 v2(75.565,14.859) 75.584,14.878 76.435,14.878 C54.2@76.454,14.897 76.454,14.922 77.407,15.875 77.47,15.875 77.851,16.256 U8.1@80.148,16.256
  Mid-Layer 2 w0.508: v2(67.818,8.89) 73.855,14.927 75.497,14.927 v2(75.565,14.859)
+5Vs: C52.2 C56.2 C57.2 C63.2 C64.2 C66.2 L4.2 R77.2 T2.2 U8.8 U9.5 U12.2 U13.2 | length 85.1
  Top Layer w0.508: U8.8@91.048,16.256 91.648,16.256 93.091,17.699 v2(93.091,17.767) 94.475,17.767 94.742,18.034 94.791,17.985 C56.2@94.791,17.967 ; T2.2@91.253,6.477 v11(92.837,6.477) 93.091,6.223 U12.2@93.98,6.223 ; U12.2@93.99,6.247 93.99,6.233 U12.2@93.98,6.223 ; v11(94.488,26.035) C57.2@95.72,26.035 ; 95.123,3.923 95.123,6.223 U12.2@93.98,6.223 ; U9.5@102.219,22.765 102.219,22.749 101.644,23.324 C52.2@101.644,24.558 101.691,24.511 v2(102.997,24.511) ; R77.2@107.546,12.728 108.336,11.938 v11(108.839,11.938) ; L4.2@114.351,17.034 114.325,17.008 C63.2@114.325,15.327 115.407,15.327 116.154,14.58 116.141,14.567 v2(116.141,14.541) ; v2@116.332,14.351 118.364,14.351 118.999,14.986 118.999,15.875 119.623,16.499 C64.2@119.623,16.943
  Mid-Layer 2 w0.508: v11(92.837,6.477) v2@92.837,17.513 ; v2@93.091,17.78 v2(93.091,17.767) v2@92.837,17.513 ; v11(94.488,26.035) 96.012,24.511 ; v2(102.997,24.511) 96.012,24.511 ; v11@108.839,11.811 108.712,11.938 v11(108.839,11.938) ; v2(116.141,14.541) v2@116.205,14.478 ; v2@92.837,17.513 92.837,21.323 96.012,24.498 96.012,24.511
  Bottom Layer w0.508: v11(92.837,6.477) 93.98,7.62 93.98,8.89 96.139,11.049 96.95,11.049 97.94,12.04 98.656,12.04 99.646,11.049 105.537,11.049 106.426,11.938 v11(108.839,11.938) 110.744,11.938 111.506,11.176 114.173,11.176 116.141,13.144 v2(116.141,14.541)
+24V: C7.1 C8.1 C9.1 C10.1 C29.1 C30.1 C31.1 C32.1 C74.1 C75.1 C76.1 C77.2 D27.2 Q11.5 Q11.6 Q11.7 Q11.8 Q11.9@120.65,54.98 R16.2 R24.2 R33.1 R56.2 R85.2 T1.9 T1.10 T1.11 U7.33 | length 45.5
  Top Layer w0.254: U7.33@117.047,30.18 117.049,30.182 117.049,30.642 117.082,30.675 117.082,31.883 117.685,32.487 118.77,32.487 118.772,32.485 v1(118.772,32.484) ; v1@118.886,32.369 119.634,33.117 R56.2@119.634,33.998
  Top Layer w0.381: R33.1@101.644,26.31 101.665,26.289 v2(102.997,26.289) ; D27.2@105.41,18.766 105.41,18.796 106.045,18.796 106.553,19.304 v2(106.934,19.304) ; v2(106.045,32.258) R24.2@106.045,33.655
  Top Layer w0.508: 120.085,57.243 120.5,57.658 122.174,57.658 R16.2@122.174,57.67 ; R85.2@138.832,65.024 140.716,65.024 140.97,64.77
  Mid-Layer 2 w0.381: v2(102.997,26.289) 106.172,26.289 ; v2(106.045,32.258) 106.045,26.416 106.172,26.289 ; v2(106.934,19.304) 106.934,21.717 107.569,22.352 107.569,24.892 106.172,26.289
  Bottom Layer w0.508: v2(106.045,32.258) 106.172,32.385 v9(111.481,32.385) 112.751,33.655 116.205,33.655 116.586,33.274 116.637,33.274 117.427,32.484 v1(118.772,32.484)
  other v3: 114.935,38.1 114.935,40.005 116.205,41.91 114.935,43.18 116.205,44.45 114.935,45.72 114.935,48.26 132.842,48.514 116.205,49.53 133.985,50.165 114.935,50.8 132.715,51.435 135.89,51.435 114.935,52.705 116.84,52.705 137.795,53.34 114.935,54.61 116.84,54.61 132.715,54.991 133.985,55.88 135.89,55.88 137.795,55.88 114.935,56.515 116.84,56.515 132.715,56.769 133.985,57.785 135.89,57.785 137.795,57.785
AC: D9.1 D10.1 R15.2 R70.2 | length 8.8
  Top Layer w0.508: R70.2@56.261,19.685 D9.1@56.261,22.913 ; D9.1@56.261,22.86 D10.1@56.261,26.162 ; D10.1@56.261,26.924 R15.2@56.261,28.649 ; 56.642,26.29 56.642,26.865
AGND: C34.1 C35.2 C48.1 C49.2 C76.2 C77.1 NT1.2 R20.1 R61.1 R65.1 R66.1 R67.1 R68.1
  other v1: 107.95,20.574 108.966,20.574 113.538,23.495 107.315,27.305 107.315,28.321 107.315,29.337 107.315,30.353 107.315,31.369 107.569,33.782 114.554,34.544 124.841,34.671 107.569,34.798
  other v8: 112.903,20.701 112.141,21.209 124.714,21.209 112.903,21.59 124.079,21.895 125.349,21.895 112.141,22.098 120.015,22.098 120.904,22.098 121.793,22.098 113.157,22.479
  other v9: 120.142,20.955 113.538,32.766
BAT: C101.2 D28.2 D29.1 Q19.1 Q19.2 Q19.3 R55.1 R57.1 R59.1 | length 104.2
  Top Layer w0.254: v9@105.41,21.438 D28.2@105.41,22.477 ; v1(119.507,18.161) 119.507,18.923 119.38,19.05 119.403,19.073 R59.1@119.403,19.105 119.475,19.177 R57.1@120.84,19.177 ; v1(158.318,14.681) 159.479,14.681 D29.1@159.664,14.867
  Mid-Layer 2 w0.254: v9(105.435,21.412) 105.435,19.71 104.521,18.796 104.521,12.04 103.708,11.227 102.235,11.227 101.676,10.668 101.676,8.052 103.657,6.071 146.355,6.071 146.558,5.867 147.472,5.867 147.676,6.071 157.074,6.071 158.115,7.112 158.115,14.478 v1(158.318,14.681)
  Bottom Layer w0.254: v1(119.507,18.161) 119.507,16.212 128.861,6.858 130.429,6.858 131.191,6.096 131.318,6.096 v1(131.318,6.121)
BAT_DRV: Q13.4 Q14.4 U7.15 | length 51.9
  Top Layer w0.254: U7.15@117.547,24.38 117.547,23.169 v15(118.11,22.606) ; Q13.4@145.543,9.88 145.543,9.905 145.542,9.906 146.05,10.414 v1(146.685,10.414) ; v1(146.964,6.655) 146.964,6.452 147.32,6.096 148.288,6.096 Q14.4@148.306,6.078
  Mid-Layer 2 w0.254: v1(135.001,8.255) 144.526,8.255 v1(146.685,10.414) 148.336,8.763 148.336,8.026 v1(146.964,6.655)
  Bottom Layer w0.254: v15(118.11,22.606) 118.3,22.415 118.3,21.653 118.491,21.463 118.491,20.193 119.151,19.533 122.387,19.533 122.819,19.964 124.181,19.964 125.349,18.796 125.349,11.303 128.905,7.747 134.493,7.747 v1(135.001,8.255)
BAT_SRC: Q13.1 Q13.2 Q13.3 Q14.1 Q14.2 Q14.3 U7.16 | length 42
  Top Layer w0.254: U7.16@118.047,24.38 118.047,23.736 118.237,23.546 118.237,23.49 118.46,23.266 118.974,23.266 v9(119.253,22.987)
  Mid-Layer 2 w0.254: v1(130.556,10.287) 133.604,7.239 145.796,7.239 v1(146.812,8.255)
  Bottom Layer w0.254: v9(119.253,22.987) 119.253,20.701 119.761,20.193 122.365,20.193 122.619,20.447 124.968,20.447 126.365,19.05 126.365,12.573 128.27,12.573 v1(130.556,10.287)
Bias: C13.1 D11.2 D13.2 Q4.2 R6.1 R10.1 | length 86.8
  Top Layer w0.508: C13.1@61.054,19.558 61.341,19.845 v13(61.341,21.209) ; Q4.2@63.01,44.978 63.435,44.553 63.435,44.196 ; D13.2@63.435,43.308 63.435,44.196 ; v2(64.516,44.196) 63.435,44.196 ; R10.1@72.225,19.558 72.263,19.558 72.263,18.174 v2(72.276,18.186) ; D11.2@73.068,31.308 73.101,31.275 74.008,31.275 v11(74.041,31.242) ; R6.1@80.175,23.495 v11(81.153,23.495)
  Mid-Layer 2 w0.508: v13(61.341,21.209) 61.341,26.289 61.976,26.924 ; v2@72.276,18.161 v2@72.25,18.186 ; v2(72.276,18.186) v2@72.25,18.186 ; v11(81.153,23.495) 81.153,30.48 80.391,31.242 v11(74.041,31.242) 67.564,31.242 63.119,35.687 63.119,42.799 v2(64.516,44.196) 60.96,44.196 59.436,42.672 59.436,34.798 61.976,32.258 61.976,26.924 ; 61.976,26.924 70.714,18.186 v2@72.25,18.186
BQ_CE: J3.5 R20.2 U7.7 | length 48.9
  Top Layer w0.254: R20.2@110.401,28.702 110.426,28.702 111.836,27.292 111.836,26.655 112.253,26.238 113.053,26.238 113.344,26.53 U7.7@114.897,26.53
  Mid-Layer 2 w0.254: v1(110.49,28.677) 110.49,29.21 110.871,29.591 112.141,29.591 112.522,29.21 115.443,29.21 116.664,30.431 116.664,34.749 119.507,37.592 119.507,44.196 120.523,45.212 120.523,54.864 121.793,56.134 121.793,60.579 122.641,61.427 J3.5@124.53,61.427
BQ_INT: J3.8 R82.1 U7.3 | length 58.5
  Top Layer w0.254: v1(113.055,29.972) 113.132,29.972 113.487,29.616 113.487,28.778 113.741,28.524 114.884,28.524 114.89,28.53 U7.3@114.897,28.53
  Top Layer w0.381: J3.8@124.714,69.088 125.73,70.104 125.73,71.062 125.749,71.082 125.749,71.882 125.73,71.901 125.73,73.602 125.749,73.622 125.749,74.422 125.73,74.441 125.73,74.93 126.492,75.692 127.508,75.692 128.016,76.2 128.016,77.081 R82.1@128.104,77.169
  Top Layer w0.508: J3.8@124.53,69.047 124.673,69.047 J3.8@124.714,69.088
  Mid-Layer 2 w0.254: v1(113.055,29.972) 115.523,29.972 116.181,30.631 116.181,35.282 118.999,38.1 118.999,44.45 119.888,45.339 119.888,55.372 121.031,56.515 121.031,65.548 J3.8@124.53,69.047
CGND: C1.2 C11.2 C12.2 C13.2 C17.2 C18.2 C20.2 C21.2 C22.2 C26.2 C53.1 C54.1 C55.1 C60.1 C61.1 C67.1 C100.2 D7.2 D8.2 D14.2 NT2.1 Q7.2 Q100.2 R25.1 R26.1 R36.1 R75.1 R101.2 T1.7 T2.5 U1.3 U3.6 U4.3 U8.3 U8.4 U10.1
  other v2: 66.294,3.937 67.818,3.937 66.294,5.207 78.486,5.334 72.898,7.62 79.248,7.874 80.518,7.874 71.882,10.922 74.676,11.43 76.2,11.43 77.597,11.43 78.994,11.43 80.264,11.43 61.214,17.653 62.738,17.653 64.008,17.653 65.278,17.653 66.548,17.653 75.946,17.78 77.597,17.907 78.74,18.415 65.278,21.336 53.594,39.878 54.864,39.878 64.516,39.878 64.516,41.148 64.516,42.418 43.434,44.958 58.166,46.482 58.166,47.879 50.292,49.022 50.292,50.292 58.166,50.546 45.212,51.308 50.292,51.562 58.166,52.07 64.516,52.578 58.166,53.34 62.738,54.102 64.516,54.102 45.466,54.356 46.736,54.356 48.26,56.388
  other v4: 64.516,46.228 64.516,47.244 36.322,54.61 37.338,54.61 38.608,54.61 39.624,54.61
  other v11: 79.756,5.334 78.359,13.335 52.578,45.212
  other v13: 68.834,17.653 69.469,22.987
DRV_SUP: C47.1 D18.2 D19.2 R54.2 U7.23 | length 18.4
  Top Layer w0.254: U7.23@119.697,27.03 120.298,27.03 120.447,26.881 120.447,26.731 120.838,26.34 121.478,26.34 122.321,27.183 122.321,27.497 123.538,28.714 R54.2@123.538,28.739 125.603,26.674 C47.1@125.603,26.441 ; C47.1@125.603,26.416 C47.1@125.603,26.441 ; v1(127.025,26.467) 125.628,26.467 C47.1@125.603,26.441 ; D19.2@133.18,26.289 D18.2@133.18,28.194
  Bottom Layer w0.254: v1(127.025,26.467) 127.025,26.441 127.813,27.229 v1(133.198,27.229)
